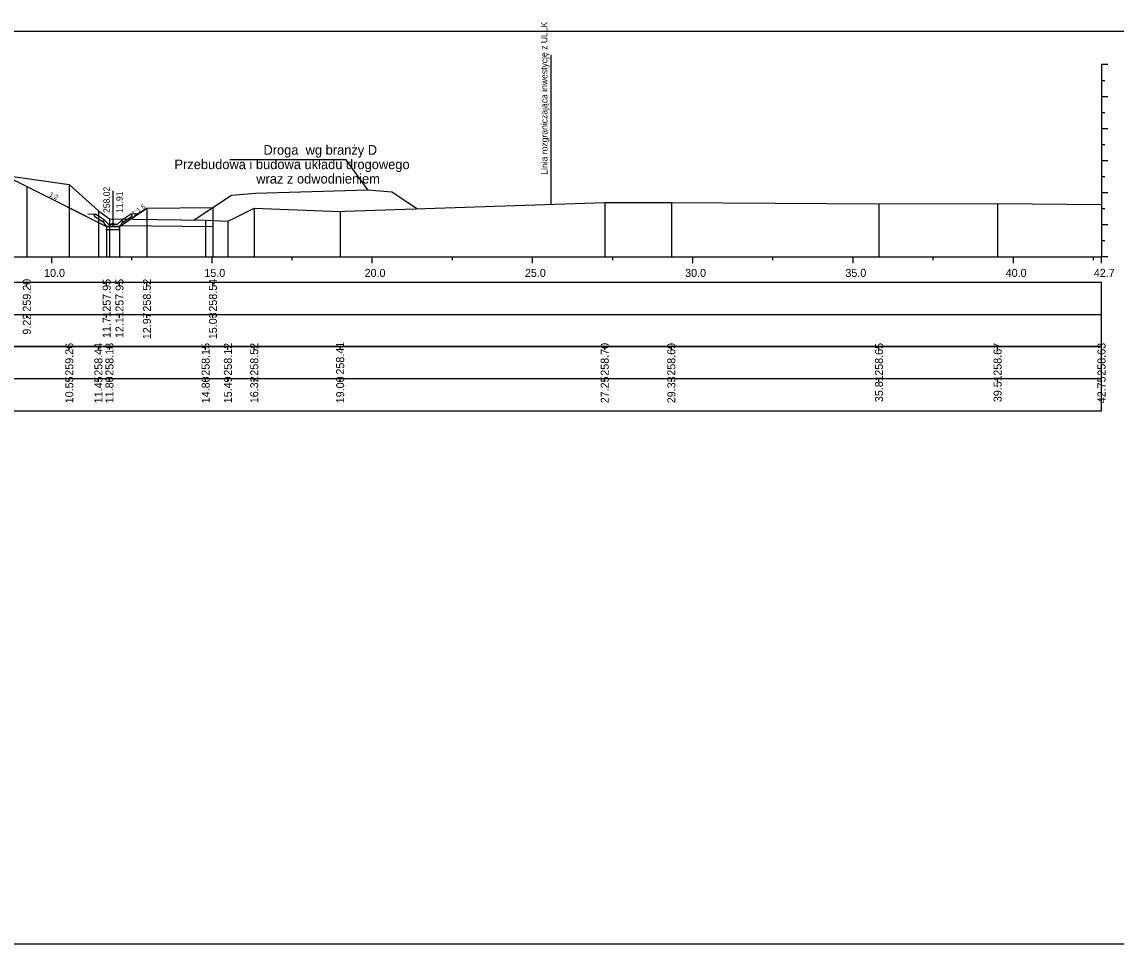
# Model space of a CAD drawing. Extents: x 6516023 to 6560129, y 5513077 to 5529206.
# Drawn here: x 6517046.78 to 6517080.92, y 5514484.66 to 5514513.44 of the extents above; entities that cross this region are included whole.
import ezdxf

# ---------------------------------------------------------------- set-up
doc = ezdxf.new("R2010")
doc.units = 0
for name, color, linetype in [('IR_default', 7, 'Continuous'), ('TOR_PRZEK_P-inne branze', 7, 'Continuous'), ('TOR_PRZEK_P-odwodnienie', 7, 'Continuous'), ('TOR_PRZEK_P-opisy', 7, 'Continuous'), ('TOR_PRZEK_P-tabelka istniejace', 7, 'Continuous'), ('TOR_PRZEK_P-tabelka projektowane', 7, 'Continuous'), ('TOR_PRZEK_P-teren istniejacy', 7, 'Continuous'), ('TOR_PRZEK_P-uklad odniesienia', 7, 'Continuous'), ('TOR_PRZEK_P-warstwa ochronna II', 7, 'Continuous'), ('TOR_PS_T-granica PKP-projektowana', 7, 'Continuous'), ('TOR_PS_T-skarpy projektowane', 7, 'Continuous'), ('TOR_RAMKI-ramka+tabelka 1', 7, 'Continuous')]:
    doc.layers.add(name, color=color, linetype=linetype)

msp = doc.modelspace()

# ---------------------------------------------------------------- linework, layer by layer
at = {"layer": 'IR_default'}
msp.add_lwpolyline([(6517046.498, 5514508.52), (6517046.933, 5514508.302), (6517048.178, 5514507.68), (6517049.424, 5514507.057), (6517049.624, 5514507.057), (6517049.824, 5514507.057), (6517050.117, 5514507.252), (6517050.409, 5514507.447), (6517050.544, 5514507.537), (6517050.679, 5514507.627), (6517052.742, 5514507.647)], dxfattribs=at)
at = {"layer": 'TOR_PRZEK_P-inne branze'}
for p, q in [((6517056.897, 5514509.134), (6517053.273, 5514509.134)), ((6517057.573, 5514508.2), (6517056.897, 5514509.134))]:
    msp.add_line(p, q, dxfattribs=at)
msp.add_lwpolyline([(6517052.159, 5514507.258), (6517053.323, 5514508.035), (6517054.073, 5514508.095), (6517055.823, 5514508.147), (6517057.573, 5514508.2), (6517058.323, 5514508.14), (6517059.12, 5514507.609)], dxfattribs=at)
at = {"layer": 'TOR_PRZEK_P-odwodnienie'}
for p, q in [((6517049.624, 5514507.127), (6517049.624, 5514508.171)), ((6517049.315, 5514507.186), (6517049.054, 5514507.36)), ((6517049.36, 5514507.252), (6517049.079, 5514507.439)), ((6517049.889, 5514507.252), (6517050.169, 5514507.439)), ((6517049.933, 5514507.186), (6517050.194, 5514507.36)), ((6517049.326, 5514507.202), (6517049.315, 5514507.186)), ((6517049.317, 5514507.222), (6517049.364, 5514507.246)), ((6517049.36, 5514507.252), (6517049.351, 5514507.24)), ((6517049.484, 5514507.127), (6517049.364, 5514507.246)), ((6517049.434, 5514507.057), (6517049.814, 5514507.057)), ((6517049.484, 5514507.127), (6517049.764, 5514507.127)), ((6517049.764, 5514507.127), (6517049.884, 5514507.246)), ((6517049.884, 5514507.246), (6517049.932, 5514507.222)), ((6517049.889, 5514507.252), (6517049.897, 5514507.24)), ((6517049.922, 5514507.202), (6517049.933, 5514507.186))]:
    msp.add_line(p, q, dxfattribs=at)
for points in [[(6517048.833, 5514507.451), (6517049.079, 5514507.439)], [(6517049.029, 5514507.413), (6517049.079, 5514507.439)], [(6517049.029, 5514507.413), (6517049.054, 5514507.36)], [(6517050.416, 5514507.451), (6517050.169, 5514507.439)], [(6517050.219, 5514507.413), (6517050.169, 5514507.439)], [(6517050.219, 5514507.413), (6517050.194, 5514507.36)], [(6517049.351, 5514507.24), (6517049.316, 5514507.221)], [(6517049.316, 5514507.221), (6517049.326, 5514507.202)], [(6517049.364, 5514507.127), (6517049.317, 5514507.222)], [(6517049.434, 5514507.057), (6517049.364, 5514507.127)], [(6517049.424, 5514507.057), (6517049.424, 5514507.057), (6517049.424, 5514507.057), (6517049.424, 5514507.056), (6517049.424, 5514507.057), (6517049.425, 5514507.056), (6517049.424, 5514507.057), (6517049.425, 5514507.057)], [(6517049.425, 5514507.056), (6517049.424, 5514507.057), (6517049.425, 5514507.056), (6517049.424, 5514507.056), (6517049.425, 5514507.056), (6517049.425, 5514507.056), (6517049.425, 5514507.056), (6517049.425, 5514507.057)], [(6517049.824, 5514507.057), (6517049.424, 5514507.057), (6517049.424, 5514506.957), (6517049.824, 5514506.957), (6517049.824, 5514507.057)], [(6517049.814, 5514507.057), (6517049.884, 5514507.127)], [(6517049.824, 5514507.057), (6517049.824, 5514507.057), (6517049.824, 5514507.057), (6517049.824, 5514507.056), (6517049.824, 5514507.057), (6517049.825, 5514507.056), (6517049.824, 5514507.057), (6517049.825, 5514507.057)], [(6517049.825, 5514507.056), (6517049.824, 5514507.057), (6517049.825, 5514507.056), (6517049.824, 5514507.056), (6517049.825, 5514507.056), (6517049.825, 5514507.056), (6517049.825, 5514507.056), (6517049.825, 5514507.057)], [(6517049.884, 5514507.127), (6517049.932, 5514507.222)], [(6517049.897, 5514507.24), (6517049.932, 5514507.221)], [(6517049.932, 5514507.221), (6517049.922, 5514507.202)]]:
    msp.add_lwpolyline(points, dxfattribs=at)
msp.add_circle((6517049.624, 5514507.127), 0.035, dxfattribs=at)
at = {"layer": 'TOR_PRZEK_P-tabelka istniejace'}
for p, q in [((6517048.26, 5514503.206), (6517048.26, 5514503.306)), ((6517049.168, 5514503.206), (6517049.168, 5514503.306)), ((6517049.512, 5514503.206), (6517049.512, 5514503.306)), ((6517052.513, 5514503.206), (6517052.513, 5514503.306)), ((6517053.208, 5514503.206), (6517053.208, 5514503.306)), ((6517054.029, 5514503.206), (6517054.029, 5514503.306)), ((6517056.71, 5514503.206), (6517056.71, 5514503.306)), ((6517064.964, 5514503.206), (6517064.964, 5514503.306)), ((6517067.043, 5514503.206), (6517067.043, 5514503.306)), ((6517073.521, 5514503.206), (6517073.521, 5514503.306)), ((6517077.221, 5514503.206), (6517077.221, 5514503.306)), ((6517080.463, 5514503.206), (6517080.463, 5514503.306)), ((6516996.663, 5514502.306), (6517080.463, 5514502.306)), ((6517048.26, 5514502.206), (6517048.26, 5514502.306)), ((6517049.168, 5514502.206), (6517049.168, 5514502.306)), ((6517049.512, 5514502.206), (6517049.512, 5514502.306)), ((6517052.513, 5514502.206), (6517052.513, 5514502.306)), ((6517053.208, 5514502.206), (6517053.208, 5514502.306)), ((6517054.029, 5514502.206), (6517054.029, 5514502.306)), ((6517056.71, 5514502.206), (6517056.71, 5514502.306)), ((6517064.964, 5514502.206), (6517064.964, 5514502.306)), ((6517067.043, 5514502.206), (6517067.043, 5514502.306)), ((6517073.521, 5514502.206), (6517073.521, 5514502.306)), ((6517077.221, 5514502.206), (6517077.221, 5514502.306)), ((6517080.463, 5514502.206), (6517080.463, 5514502.306))]:
    msp.add_line(p, q, dxfattribs=at)
for points in [[(6517048.26, 5514508.364), (6517048.26, 5514506.306), (6517048.26, 5514506.176), (6517048.26, 5514506.106)], [(6517064.964, 5514507.808), (6517064.964, 5514506.306), (6517064.964, 5514506.176), (6517064.964, 5514506.106)], [(6517067.043, 5514507.799), (6517067.043, 5514506.306), (6517067.043, 5514506.176), (6517067.043, 5514506.106)], [(6517073.521, 5514507.757), (6517073.521, 5514506.306), (6517073.521, 5514506.176), (6517073.521, 5514506.106)], [(6517077.221, 5514507.772), (6517077.221, 5514506.306), (6517077.221, 5514506.176), (6517077.221, 5514506.106)], [(6517080.463, 5514507.741), (6517080.463, 5514506.306), (6517080.463, 5514506.176), (6517080.463, 5514506.106)], [(6517049.168, 5514507.544), (6517049.168, 5514506.306), (6517049.168, 5514506.176), (6517049.168, 5514506.106)], [(6517054.029, 5514507.627), (6517054.029, 5514506.306), (6517054.029, 5514506.176), (6517054.029, 5514506.106)], [(6517056.71, 5514507.518), (6517056.71, 5514506.306), (6517056.71, 5514506.176), (6517056.71, 5514506.106)], [(6517049.512, 5514507.29), (6517049.512, 5514506.306), (6517049.512, 5514506.176), (6517049.512, 5514506.106)], [(6517052.513, 5514507.254), (6517052.513, 5514506.306), (6517052.513, 5514506.176), (6517052.513, 5514506.106)], [(6517053.208, 5514507.225), (6517053.208, 5514506.306), (6517053.208, 5514506.176), (6517053.208, 5514506.106)]]:
    msp.add_lwpolyline(points, dxfattribs=at)
msp.add_lwpolyline([(6516996.663, 5514503.306), (6516996.663, 5514501.306), (6517080.463, 5514501.306), (6517080.463, 5514503.306)], close=True, dxfattribs=at)
at = {"layer": 'TOR_PRZEK_P-tabelka projektowane'}
for p, q in [((6517046.933, 5514505.206), (6517046.933, 5514505.306)), ((6517049.425, 5514505.206), (6517049.425, 5514505.306)), ((6517049.825, 5514505.206), (6517049.825, 5514505.306)), ((6517050.68, 5514505.206), (6517050.68, 5514505.306)), ((6517052.741, 5514505.206), (6517052.741, 5514505.306)), ((6516996.663, 5514504.306), (6517080.463, 5514504.306)), ((6517046.933, 5514504.206), (6517046.933, 5514504.306)), ((6517049.425, 5514504.206), (6517049.425, 5514504.306)), ((6517049.825, 5514504.206), (6517049.825, 5514504.306)), ((6517050.68, 5514504.206), (6517050.68, 5514504.306)), ((6517052.741, 5514504.206), (6517052.741, 5514504.306))]:
    msp.add_line(p, q, dxfattribs=at)
for points in [[(6517046.933, 5514508.302), (6517046.933, 5514506.306), (6517046.933, 5514506.176), (6517046.933, 5514506.106)], [(6517050.68, 5514507.626), (6517050.68, 5514506.306), (6517050.68, 5514506.176), (6517050.68, 5514506.106)], [(6517052.741, 5514507.647), (6517052.741, 5514506.306), (6517052.741, 5514506.176), (6517052.741, 5514506.106)], [(6517049.425, 5514507.056), (6517049.425, 5514506.306), (6517049.425, 5514506.176), (6517049.425, 5514506.106)], [(6517049.825, 5514507.056), (6517049.825, 5514506.306), (6517049.825, 5514506.176), (6517049.825, 5514506.106)]]:
    msp.add_lwpolyline(points, dxfattribs=at)
msp.add_lwpolyline([(6516996.663, 5514505.306), (6516996.663, 5514503.306), (6517080.463, 5514503.306), (6517080.463, 5514505.306)], close=True, dxfattribs=at)
at = {"layer": 'TOR_PRZEK_P-teren istniejacy'}
msp.add_lwpolyline([(6517045.323, 5514508.779), (6517048.26, 5514508.364), (6517049.168, 5514507.544), (6517049.512, 5514507.29), (6517052.513, 5514507.254), (6517053.208, 5514507.225), (6517053.404, 5514507.313), (6517054.029, 5514507.627), (6517056.71, 5514507.518), (6517056.865, 5514507.532), (6517064.964, 5514507.808), (6517067.043, 5514507.799), (6517073.521, 5514507.757), (6517077.221, 5514507.772), (6517080.463, 5514507.741)], dxfattribs=at)
at = {"layer": 'TOR_PRZEK_P-uklad odniesienia'}
for p, q in [((6517080.463, 5514512.106), (6517080.463, 5514506.106)), ((6517080.663, 5514512.106), (6517080.463, 5514512.106)), ((6517080.563, 5514511.606), (6517080.463, 5514511.606)), ((6517080.663, 5514511.106), (6517080.463, 5514511.106)), ((6517080.563, 5514510.606), (6517080.463, 5514510.606)), ((6517080.663, 5514510.106), (6517080.463, 5514510.106)), ((6517080.563, 5514509.606), (6517080.463, 5514509.606)), ((6517080.663, 5514509.106), (6517080.463, 5514509.106)), ((6517080.563, 5514508.606), (6517080.463, 5514508.606)), ((6517080.663, 5514508.106), (6517080.463, 5514508.106)), ((6517080.563, 5514507.606), (6517080.463, 5514507.606)), ((6517080.663, 5514507.106), (6517080.463, 5514507.106)), ((6517080.563, 5514506.606), (6517080.463, 5514506.606)), ((6517000.463, 5514506.106), (6517080.463, 5514506.106)), ((6517047.713, 5514505.906), (6517047.713, 5514506.106)), ((6517050.213, 5514506.006), (6517050.213, 5514506.106)), ((6517052.713, 5514505.906), (6517052.713, 5514506.106)), ((6517055.213, 5514506.006), (6517055.213, 5514506.106)), ((6517057.713, 5514505.906), (6517057.713, 5514506.106)), ((6517060.213, 5514506.006), (6517060.213, 5514506.106)), ((6517062.713, 5514505.906), (6517062.713, 5514506.106)), ((6517065.213, 5514506.006), (6517065.213, 5514506.106)), ((6517067.713, 5514505.906), (6517067.713, 5514506.106)), ((6517070.213, 5514506.006), (6517070.213, 5514506.106)), ((6517072.713, 5514505.906), (6517072.713, 5514506.106)), ((6517075.213, 5514506.006), (6517075.213, 5514506.106)), ((6517077.713, 5514505.906), (6517077.713, 5514506.106)), ((6517080.213, 5514506.006), (6517080.213, 5514506.106)), ((6517080.463, 5514505.906), (6517080.463, 5514506.106)), ((6517080.663, 5514506.106), (6517080.463, 5514506.106))]:
    msp.add_line(p, q, dxfattribs=at)
at = {"layer": 'TOR_PRZEK_P-warstwa ochronna II'}
msp.add_lwpolyline([(6517021.488, 5514507.628), (6517021.657, 5514507.626), (6517022.243, 5514507.236), (6517022.643, 5514507.236), (6517023.713, 5514507.95), (6517028.734, 5514508.251), (6517029.213, 5514508.57), (6517033.213, 5514508.73), (6517035.463, 5514508.82), (6517037.713, 5514508.91), (6517038.463, 5514508.94), (6517039.713, 5514508.99), (6517039.763, 5514508.989), (6517041.013, 5514508.939), (6517041.763, 5514508.909), (6517046.063, 5514508.737), (6517046.933, 5514508.302), (6517049.425, 5514507.056), (6517049.825, 5514507.056), (6517050.68, 5514507.626), (6517052.741, 5514507.647)], dxfattribs=at)
at = {"layer": 'TOR_PS_T-granica PKP-projektowana'}
msp.add_line((6517063.29, 5514507.751), (6517063.29, 5514512.408), dxfattribs=at)
at = {"layer": 'TOR_PS_T-skarpy projektowane'}
msp.add_lwpolyline([(6517049.869, 5514507.086), (6517052.741, 5514507.052)], dxfattribs=at)
at = {"layer": 'TOR_RAMKI-ramka+tabelka 1'}
msp.add_lwpolyline([(6516907.013, 5514513.156), (6517154.513, 5514513.156), (6517154.513, 5514484.656), (6516907.013, 5514484.656)], close=True, dxfattribs=at)

# ---------------------------------------------------------------- texts
at = {"layer": 'TOR_PRZEK_P-inne branze'}
for s, p in [('Droga  wg branży D', (6517054.317, 5514509.295)), ('Przebudowa i budowa układu drogowego', (6517051.54, 5514508.845)), ('wraz z odwodnieniem ', (6517054.092, 5514508.395))]:
    msp.add_text(s, height=0.3, dxfattribs=at).set_placement(p)
at = {"layer": 'TOR_PRZEK_P-odwodnienie'}
for s, p in [('258.02', (6517049.524, 5514507.477)), ('11.91', (6517049.924, 5514507.477))]:
    msp.add_text(s, height=0.2, rotation=90, dxfattribs=at).set_placement(p)
at = {"layer": 'TOR_PRZEK_P-opisy'}
for s, rotation, p in [('1:2', 332.9299, (6517047.614, 5514508.01)), ('1:1,5', 34.0701, (6517050.275, 5514507.378))]:
    msp.add_text(s, height=0.15, rotation=rotation, dxfattribs=at).set_placement(p)
at = {"layer": 'TOR_PRZEK_P-tabelka istniejace'}
for s, p in [('259.26', (6517048.385, 5514502.398)), ('258.44', (6517049.293, 5514502.399)), ('258.18', (6517049.637, 5514502.398)), ('258.15', (6517052.638, 5514502.397)), ('258.12', (6517053.333, 5514502.4)), ('258.52', (6517054.154, 5514502.4)), ('258.41', (6517056.835, 5514502.433)), ('258.70', (6517065.089, 5514502.398)), ('258.69', (6517067.168, 5514502.398)), ('258.65', (6517073.646, 5514502.397)), ('258.67', (6517077.346, 5514502.398)), ('258.63', (6517080.588, 5514502.398)), ('10.55', (6517048.385, 5514501.537)), ('11.45', (6517049.293, 5514501.537)), ('11.80', (6517049.637, 5514501.538)), ('14.80', (6517052.638, 5514501.538)), ('15.49', (6517053.333, 5514501.538)), ('16.32', (6517054.154, 5514501.54)), ('19.00', (6517056.835, 5514501.538)), ('27.25', (6517065.089, 5514501.537)), ('29.33', (6517067.168, 5514501.538)), ('35.81', (6517073.646, 5514501.573)), ('39.51', (6517077.346, 5514501.573)), ('42.75', (6517080.588, 5514501.537))]:
    msp.add_text(s, height=0.25, rotation=90, dxfattribs=at).set_placement(p)
at = {"layer": 'TOR_PRZEK_P-tabelka projektowane'}
for s, p in [('259.20', (6517047.058, 5514504.398)), ('257.95', (6517049.55, 5514504.397)), ('257.95', (6517049.95, 5514504.397)), ('258.52', (6517050.805, 5514504.4)), ('258.54', (6517052.866, 5514504.399)), ('9.22', (6517047.058, 5514503.68)), ('11.71', (6517049.55, 5514503.573)), ('12.11', (6517049.95, 5514503.573)), ('12.97', (6517050.805, 5514503.538)), ('15.03', (6517052.866, 5514503.538))]:
    msp.add_text(s, height=0.25, rotation=90, dxfattribs=at).set_placement(p)
at = {"layer": 'TOR_PRZEK_P-uklad odniesienia'}
for s, p in [('10.0', (6517047.474, 5514505.481)), ('15.0', (6517052.474, 5514505.481)), ('20.0', (6517057.474, 5514505.481)), ('25.0', (6517062.474, 5514505.481)), ('30.0', (6517067.474, 5514505.481)), ('35.0', (6517072.474, 5514505.481)), ('40.0', (6517077.474, 5514505.481)), ('42.7', (6517080.224, 5514505.481))]:
    msp.add_text(s, height=0.25, dxfattribs=at).set_placement(p)
at = {"layer": 'TOR_PS_T-granica PKP-projektowana'}
msp.add_text('Linia rozgraniczająca inwestycję z ULLK', height=0.2, rotation=90.0511, dxfattribs=at).set_placement((6517063.179, 5514508.672))

doc.saveas('drawing.dxf')
